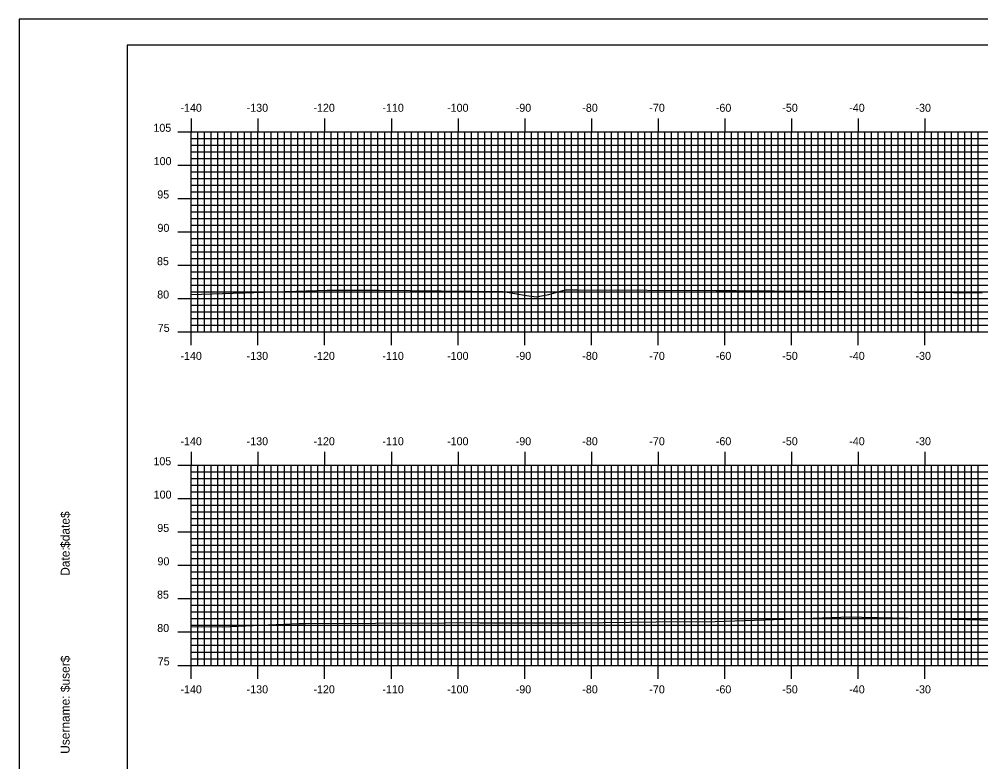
# Model space of a CAD drawing. Extents: x 2453 to 2796, y -1658 to -1438.
# Drawn here: x 2452.9 to 2597.1, y -1549.1 to -1437.7 of the extents above; entities that cross this region are included whole.
import ezdxf

# ---------------------------------------------------------------- set-up
doc = ezdxf.new("R2010")
doc.units = 0
for name, color, linetype in [('BORDER', 7, 'Continuous'), ('H_V ANNOTATION', 7, 'Continuous'), ('MAJOR', 7, 'Continuous'), ('MINOR', 7, 'Continuous'), ('PLOT BOUNDARY', 7, 'Continuous'), ('S_Roadway_Centerline', 7, 'Continuous')]:
    doc.layers.add(name, color=color, linetype=linetype)

msp = doc.modelspace()

# ---------------------------------------------------------------- linework, layer by layer
at = {"layer": 'BORDER'}
msp.add_lwpolyline([(2469.1, -1651.6), (2789.1, -1651.6), (2789.1, -1441.6), (2469.1, -1441.6)], close=True, dxfattribs=at)
at = {"layer": 'MAJOR'}
for p, q in [((2478.7, -1452.6), (2478.7, -1454.6)), ((2488.7, -1452.6), (2488.7, -1454.6)), ((2498.7, -1452.6), (2498.7, -1454.6)), ((2508.7, -1452.6), (2508.7, -1454.6)), ((2518.7, -1452.6), (2518.7, -1454.6)), ((2528.7, -1452.6), (2528.7, -1454.6)), ((2538.7, -1452.6), (2538.7, -1454.6)), ((2548.7, -1452.6), (2548.7, -1454.6)), ((2558.7, -1452.6), (2558.7, -1454.6)), ((2568.7, -1452.6), (2568.7, -1454.6)), ((2578.7, -1452.6), (2578.7, -1454.6)), ((2588.7, -1452.6), (2588.7, -1454.6)), ((2476.7, -1454.6), (2478.7, -1454.6)), ((2478.7, -1454.6), (2758.7, -1454.6)), ((2478.7, -1484.6), (2478.7, -1454.6)), ((2478.7, -1484.6), (2478.7, -1454.6)), ((2478.7, -1454.6), (2758.7, -1454.6)), ((2488.7, -1484.6), (2488.7, -1454.6)), ((2498.7, -1484.6), (2498.7, -1454.6)), ((2508.7, -1484.6), (2508.7, -1454.6)), ((2518.7, -1484.6), (2518.7, -1454.6)), ((2528.7, -1484.6), (2528.7, -1454.6)), ((2538.7, -1484.6), (2538.7, -1454.6)), ((2548.7, -1484.6), (2548.7, -1454.6)), ((2558.7, -1484.6), (2558.7, -1454.6)), ((2568.7, -1484.6), (2568.7, -1454.6)), ((2578.7, -1484.6), (2578.7, -1454.6)), ((2588.7, -1484.6), (2588.7, -1454.6)), ((2476.7, -1459.6), (2478.7, -1459.6)), ((2478.7, -1459.6), (2758.7, -1459.6)), ((2476.7, -1464.6), (2478.7, -1464.6)), ((2478.7, -1464.6), (2758.7, -1464.6)), ((2476.7, -1469.6), (2478.7, -1469.6)), ((2478.7, -1469.6), (2758.7, -1469.6)), ((2476.7, -1474.6), (2478.7, -1474.6)), ((2478.7, -1474.6), (2758.7, -1474.6)), ((2476.7, -1479.6), (2478.7, -1479.6)), ((2478.7, -1479.6), (2758.7, -1479.6)), ((2476.7, -1484.6), (2478.7, -1484.6)), ((2478.7, -1484.6), (2758.7, -1484.6)), ((2478.7, -1484.6), (2758.7, -1484.6)), ((2478.7, -1486.61), (2478.7, -1484.6)), ((2488.7, -1486.61), (2488.7, -1484.6)), ((2498.7, -1486.61), (2498.7, -1484.6)), ((2508.7, -1486.61), (2508.7, -1484.6)), ((2518.7, -1486.61), (2518.7, -1484.6)), ((2528.7, -1486.61), (2528.7, -1484.6)), ((2538.7, -1486.61), (2538.7, -1484.6)), ((2548.7, -1486.61), (2548.7, -1484.6)), ((2558.7, -1486.61), (2558.7, -1484.6)), ((2568.7, -1486.61), (2568.7, -1484.6)), ((2578.7, -1486.61), (2578.7, -1484.6)), ((2588.7, -1486.61), (2588.7, -1484.6)), ((2478.7, -1502.6), (2478.7, -1504.6)), ((2488.7, -1502.6), (2488.7, -1504.6)), ((2498.7, -1502.6), (2498.7, -1504.6)), ((2508.7, -1502.6), (2508.7, -1504.6)), ((2518.7, -1502.6), (2518.7, -1504.6)), ((2528.7, -1502.6), (2528.7, -1504.6)), ((2538.7, -1502.6), (2538.7, -1504.6)), ((2548.7, -1502.6), (2548.7, -1504.6)), ((2558.7, -1502.6), (2558.7, -1504.6)), ((2568.7, -1502.6), (2568.7, -1504.6)), ((2578.7, -1502.6), (2578.7, -1504.6)), ((2588.7, -1502.6), (2588.7, -1504.6)), ((2476.7, -1504.6), (2478.7, -1504.6)), ((2478.7, -1504.6), (2758.7, -1504.6)), ((2478.7, -1534.6), (2478.7, -1504.6)), ((2478.7, -1534.6), (2478.7, -1504.6)), ((2478.7, -1504.6), (2758.7, -1504.6)), ((2488.7, -1534.6), (2488.7, -1504.6)), ((2498.7, -1534.6), (2498.7, -1504.6)), ((2508.7, -1534.6), (2508.7, -1504.6)), ((2518.7, -1534.6), (2518.7, -1504.6)), ((2528.7, -1534.6), (2528.7, -1504.6)), ((2538.7, -1534.6), (2538.7, -1504.6)), ((2548.7, -1534.6), (2548.7, -1504.6)), ((2558.7, -1534.6), (2558.7, -1504.6)), ((2568.7, -1534.6), (2568.7, -1504.6)), ((2578.7, -1534.6), (2578.7, -1504.6)), ((2588.7, -1534.6), (2588.7, -1504.6)), ((2476.7, -1509.6), (2478.7, -1509.6)), ((2478.7, -1509.6), (2758.7, -1509.6)), ((2476.7, -1514.6), (2478.7, -1514.6)), ((2478.7, -1514.6), (2758.7, -1514.6)), ((2476.7, -1519.6), (2478.7, -1519.6)), ((2478.7, -1519.6), (2758.7, -1519.6)), ((2476.7, -1524.6), (2478.7, -1524.6)), ((2478.7, -1524.6), (2758.7, -1524.6)), ((2476.7, -1529.6), (2478.7, -1529.6)), ((2478.7, -1529.6), (2758.7, -1529.6)), ((2476.7, -1534.6), (2478.7, -1534.6)), ((2478.7, -1534.6), (2758.7, -1534.6)), ((2478.7, -1534.6), (2758.7, -1534.6)), ((2478.7, -1536.61), (2478.7, -1534.6)), ((2488.7, -1536.61), (2488.7, -1534.6)), ((2498.7, -1536.61), (2498.7, -1534.6)), ((2508.7, -1536.61), (2508.7, -1534.6)), ((2518.7, -1536.61), (2518.7, -1534.6)), ((2528.7, -1536.61), (2528.7, -1534.6)), ((2538.7, -1536.61), (2538.7, -1534.6)), ((2548.7, -1536.61), (2548.7, -1534.6)), ((2558.7, -1536.61), (2558.7, -1534.6)), ((2568.7, -1536.61), (2568.7, -1534.6)), ((2578.7, -1536.61), (2578.7, -1534.6)), ((2588.7, -1536.61), (2588.7, -1534.6))]:
    msp.add_line(p, q, dxfattribs=at)
at = {"layer": 'MINOR'}
for p, q in [((2478.7, -1455.6), (2758.7, -1455.6)), ((2478.7, -1455.6), (2480.7, -1455.6)), ((2479.7, -1484.6), (2479.7, -1454.6)), ((2480.7, -1484.6), (2480.7, -1454.6)), ((2481.7, -1484.6), (2481.7, -1454.6)), ((2482.7, -1484.6), (2482.7, -1454.6)), ((2483.7, -1484.6), (2483.7, -1454.6)), ((2484.7, -1484.6), (2484.7, -1454.6)), ((2485.7, -1484.6), (2485.7, -1454.6)), ((2486.7, -1484.6), (2486.7, -1454.6)), ((2487.7, -1484.6), (2487.7, -1454.6)), ((2489.7, -1484.6), (2489.7, -1454.6)), ((2490.7, -1484.6), (2490.7, -1454.6)), ((2491.7, -1484.6), (2491.7, -1454.6)), ((2492.7, -1484.6), (2492.7, -1454.6)), ((2493.7, -1484.6), (2493.7, -1454.6)), ((2494.7, -1484.6), (2494.7, -1454.6)), ((2495.7, -1484.6), (2495.7, -1454.6)), ((2496.7, -1484.6), (2496.7, -1454.6)), ((2497.7, -1484.6), (2497.7, -1454.6)), ((2499.7, -1484.6), (2499.7, -1454.6)), ((2500.7, -1484.6), (2500.7, -1454.6)), ((2501.7, -1484.6), (2501.7, -1454.6)), ((2502.7, -1484.6), (2502.7, -1454.6)), ((2503.7, -1484.6), (2503.7, -1454.6)), ((2504.7, -1484.6), (2504.7, -1454.6)), ((2505.7, -1484.6), (2505.7, -1454.6)), ((2506.7, -1484.6), (2506.7, -1454.6)), ((2507.7, -1484.6), (2507.7, -1454.6)), ((2509.7, -1484.6), (2509.7, -1454.6)), ((2510.7, -1484.6), (2510.7, -1454.6)), ((2511.7, -1484.6), (2511.7, -1454.6)), ((2512.7, -1484.6), (2512.7, -1454.6)), ((2513.7, -1484.6), (2513.7, -1454.6)), ((2514.7, -1484.6), (2514.7, -1454.6)), ((2515.7, -1484.6), (2515.7, -1454.6)), ((2516.7, -1484.6), (2516.7, -1454.6)), ((2517.7, -1484.6), (2517.7, -1454.6)), ((2519.7, -1484.6), (2519.7, -1454.6)), ((2520.7, -1484.6), (2520.7, -1454.6)), ((2521.7, -1484.6), (2521.7, -1454.6)), ((2522.7, -1484.6), (2522.7, -1454.6)), ((2523.7, -1484.6), (2523.7, -1454.6)), ((2524.7, -1484.6), (2524.7, -1454.6)), ((2525.7, -1484.6), (2525.7, -1454.6)), ((2526.7, -1484.6), (2526.7, -1454.6)), ((2527.7, -1484.6), (2527.7, -1454.6)), ((2529.7, -1484.6), (2529.7, -1454.6)), ((2530.7, -1484.6), (2530.7, -1454.6)), ((2531.7, -1484.6), (2531.7, -1454.6)), ((2532.7, -1484.6), (2532.7, -1454.6)), ((2533.7, -1484.6), (2533.7, -1454.6)), ((2534.7, -1484.6), (2534.7, -1454.6)), ((2535.7, -1484.6), (2535.7, -1454.6)), ((2536.7, -1484.6), (2536.7, -1454.6)), ((2537.7, -1484.6), (2537.7, -1454.6)), ((2539.7, -1484.6), (2539.7, -1454.6)), ((2540.7, -1484.6), (2540.7, -1454.6)), ((2541.7, -1484.6), (2541.7, -1454.6)), ((2542.7, -1484.6), (2542.7, -1454.6)), ((2543.7, -1484.6), (2543.7, -1454.6)), ((2544.7, -1484.6), (2544.7, -1454.6)), ((2545.7, -1484.6), (2545.7, -1454.6)), ((2546.7, -1484.6), (2546.7, -1454.6)), ((2547.7, -1484.6), (2547.7, -1454.6)), ((2549.7, -1484.6), (2549.7, -1454.6)), ((2550.7, -1484.6), (2550.7, -1454.6)), ((2551.7, -1484.6), (2551.7, -1454.6)), ((2552.7, -1484.6), (2552.7, -1454.6)), ((2553.7, -1484.6), (2553.7, -1454.6)), ((2554.7, -1484.6), (2554.7, -1454.6)), ((2555.7, -1484.6), (2555.7, -1454.6)), ((2556.7, -1484.6), (2556.7, -1454.6)), ((2557.7, -1484.6), (2557.7, -1454.6)), ((2559.7, -1484.6), (2559.7, -1454.6)), ((2560.7, -1484.6), (2560.7, -1454.6)), ((2561.7, -1484.6), (2561.7, -1454.6)), ((2562.7, -1484.6), (2562.7, -1454.6)), ((2563.7, -1484.6), (2563.7, -1454.6)), ((2564.7, -1484.6), (2564.7, -1454.6)), ((2565.7, -1484.6), (2565.7, -1454.6)), ((2566.7, -1484.6), (2566.7, -1454.6)), ((2567.7, -1484.6), (2567.7, -1454.6)), ((2569.7, -1484.6), (2569.7, -1454.6)), ((2570.7, -1484.6), (2570.7, -1454.6)), ((2571.7, -1484.6), (2571.7, -1454.6)), ((2572.7, -1484.6), (2572.7, -1454.6)), ((2573.7, -1484.6), (2573.7, -1454.6)), ((2574.7, -1484.6), (2574.7, -1454.6)), ((2575.7, -1484.6), (2575.7, -1454.6)), ((2576.7, -1484.6), (2576.7, -1454.6)), ((2577.7, -1484.6), (2577.7, -1454.6)), ((2579.7, -1484.6), (2579.7, -1454.6)), ((2580.7, -1484.6), (2580.7, -1454.6)), ((2581.7, -1484.6), (2581.7, -1454.6)), ((2582.7, -1484.6), (2582.7, -1454.6)), ((2583.7, -1484.6), (2583.7, -1454.6)), ((2584.7, -1484.6), (2584.7, -1454.6)), ((2585.7, -1484.6), (2585.7, -1454.6)), ((2586.7, -1484.6), (2586.7, -1454.6)), ((2587.7, -1484.6), (2587.7, -1454.6)), ((2589.7, -1484.6), (2589.7, -1454.6)), ((2590.7, -1484.6), (2590.7, -1454.6)), ((2591.7, -1484.6), (2591.7, -1454.6)), ((2592.7, -1484.6), (2592.7, -1454.6)), ((2593.7, -1484.6), (2593.7, -1454.6)), ((2594.7, -1484.6), (2594.7, -1454.6)), ((2595.7, -1484.6), (2595.7, -1454.6)), ((2596.7, -1484.6), (2596.7, -1454.6)), ((2478.7, -1456.6), (2758.7, -1456.6)), ((2478.7, -1456.6), (2480.7, -1456.6)), ((2478.7, -1457.6), (2758.7, -1457.6)), ((2478.7, -1457.6), (2480.7, -1457.6)), ((2478.7, -1458.6), (2758.7, -1458.6)), ((2478.7, -1458.6), (2480.7, -1458.6)), ((2478.7, -1460.6), (2758.7, -1460.6)), ((2478.7, -1460.6), (2480.7, -1460.6)), ((2478.7, -1461.6), (2758.7, -1461.6)), ((2478.7, -1461.6), (2480.7, -1461.6)), ((2478.7, -1462.6), (2758.7, -1462.6)), ((2478.7, -1462.6), (2480.7, -1462.6)), ((2478.7, -1463.6), (2758.7, -1463.6)), ((2478.7, -1463.6), (2480.7, -1463.6)), ((2478.7, -1465.6), (2758.7, -1465.6)), ((2478.7, -1465.6), (2480.7, -1465.6)), ((2478.7, -1466.6), (2758.7, -1466.6)), ((2478.7, -1466.6), (2480.7, -1466.6)), ((2478.7, -1467.6), (2758.7, -1467.6)), ((2478.7, -1467.6), (2480.7, -1467.6)), ((2478.7, -1468.6), (2758.7, -1468.6)), ((2478.7, -1468.6), (2480.7, -1468.6)), ((2478.7, -1470.6), (2758.7, -1470.6)), ((2478.7, -1470.6), (2480.7, -1470.6)), ((2478.7, -1471.6), (2758.7, -1471.6)), ((2478.7, -1471.6), (2480.7, -1471.6)), ((2478.7, -1472.6), (2758.7, -1472.6)), ((2478.7, -1472.6), (2480.7, -1472.6)), ((2478.7, -1473.6), (2758.7, -1473.6)), ((2478.7, -1473.6), (2480.7, -1473.6)), ((2478.7, -1475.6), (2758.7, -1475.6)), ((2478.7, -1475.6), (2480.7, -1475.6)), ((2478.7, -1476.6), (2758.7, -1476.6)), ((2478.7, -1476.6), (2480.7, -1476.6)), ((2478.7, -1477.6), (2758.7, -1477.6)), ((2478.7, -1477.6), (2480.7, -1477.6)), ((2478.7, -1478.6), (2758.7, -1478.6)), ((2478.7, -1478.6), (2480.7, -1478.6)), ((2478.7, -1480.6), (2758.7, -1480.6)), ((2478.7, -1480.6), (2480.7, -1480.6)), ((2478.7, -1481.6), (2758.7, -1481.6)), ((2478.7, -1481.6), (2480.7, -1481.6)), ((2478.7, -1482.6), (2758.7, -1482.6)), ((2478.7, -1482.6), (2480.7, -1482.6)), ((2478.7, -1483.6), (2758.7, -1483.6)), ((2478.7, -1483.6), (2480.7, -1483.6)), ((2479.7, -1534.6), (2479.7, -1504.6)), ((2480.7, -1534.6), (2480.7, -1504.6)), ((2481.7, -1534.6), (2481.7, -1504.6)), ((2482.7, -1534.6), (2482.7, -1504.6)), ((2483.7, -1534.6), (2483.7, -1504.6)), ((2484.7, -1534.6), (2484.7, -1504.6)), ((2485.7, -1534.6), (2485.7, -1504.6)), ((2486.7, -1534.6), (2486.7, -1504.6)), ((2487.7, -1534.6), (2487.7, -1504.6)), ((2489.7, -1534.6), (2489.7, -1504.6)), ((2490.7, -1534.6), (2490.7, -1504.6)), ((2491.7, -1534.6), (2491.7, -1504.6)), ((2492.7, -1534.6), (2492.7, -1504.6)), ((2493.7, -1534.6), (2493.7, -1504.6)), ((2494.7, -1534.6), (2494.7, -1504.6)), ((2495.7, -1534.6), (2495.7, -1504.6)), ((2496.7, -1534.6), (2496.7, -1504.6)), ((2497.7, -1534.6), (2497.7, -1504.6)), ((2499.7, -1534.6), (2499.7, -1504.6)), ((2500.7, -1534.6), (2500.7, -1504.6)), ((2501.7, -1534.6), (2501.7, -1504.6)), ((2502.7, -1534.6), (2502.7, -1504.6)), ((2503.7, -1534.6), (2503.7, -1504.6)), ((2504.7, -1534.6), (2504.7, -1504.6)), ((2505.7, -1534.6), (2505.7, -1504.6)), ((2506.7, -1534.6), (2506.7, -1504.6)), ((2507.7, -1534.6), (2507.7, -1504.6)), ((2509.7, -1534.6), (2509.7, -1504.6)), ((2510.7, -1534.6), (2510.7, -1504.6)), ((2511.7, -1534.6), (2511.7, -1504.6)), ((2512.7, -1534.6), (2512.7, -1504.6)), ((2513.7, -1534.6), (2513.7, -1504.6)), ((2514.7, -1534.6), (2514.7, -1504.6)), ((2515.7, -1534.6), (2515.7, -1504.6)), ((2516.7, -1534.6), (2516.7, -1504.6)), ((2517.7, -1534.6), (2517.7, -1504.6)), ((2519.7, -1534.6), (2519.7, -1504.6)), ((2520.7, -1534.6), (2520.7, -1504.6)), ((2521.7, -1534.6), (2521.7, -1504.6)), ((2522.7, -1534.6), (2522.7, -1504.6)), ((2523.7, -1534.6), (2523.7, -1504.6)), ((2524.7, -1534.6), (2524.7, -1504.6)), ((2525.7, -1534.6), (2525.7, -1504.6)), ((2526.7, -1534.6), (2526.7, -1504.6)), ((2527.7, -1534.6), (2527.7, -1504.6)), ((2529.7, -1534.6), (2529.7, -1504.6)), ((2530.7, -1534.6), (2530.7, -1504.6)), ((2531.7, -1534.6), (2531.7, -1504.6)), ((2532.7, -1534.6), (2532.7, -1504.6)), ((2533.7, -1534.6), (2533.7, -1504.6)), ((2534.7, -1534.6), (2534.7, -1504.6)), ((2535.7, -1534.6), (2535.7, -1504.6)), ((2536.7, -1534.6), (2536.7, -1504.6)), ((2537.7, -1534.6), (2537.7, -1504.6)), ((2539.7, -1534.6), (2539.7, -1504.6)), ((2540.7, -1534.6), (2540.7, -1504.6)), ((2541.7, -1534.6), (2541.7, -1504.6)), ((2542.7, -1534.6), (2542.7, -1504.6)), ((2543.7, -1534.6), (2543.7, -1504.6)), ((2544.7, -1534.6), (2544.7, -1504.6)), ((2545.7, -1534.6), (2545.7, -1504.6)), ((2546.7, -1534.6), (2546.7, -1504.6)), ((2547.7, -1534.6), (2547.7, -1504.6)), ((2549.7, -1534.6), (2549.7, -1504.6)), ((2550.7, -1534.6), (2550.7, -1504.6)), ((2551.7, -1534.6), (2551.7, -1504.6)), ((2552.7, -1534.6), (2552.7, -1504.6)), ((2553.7, -1534.6), (2553.7, -1504.6)), ((2554.7, -1534.6), (2554.7, -1504.6)), ((2555.7, -1534.6), (2555.7, -1504.6)), ((2556.7, -1534.6), (2556.7, -1504.6)), ((2557.7, -1534.6), (2557.7, -1504.6)), ((2559.7, -1534.6), (2559.7, -1504.6)), ((2560.7, -1534.6), (2560.7, -1504.6)), ((2561.7, -1534.6), (2561.7, -1504.6)), ((2562.7, -1534.6), (2562.7, -1504.6)), ((2563.7, -1534.6), (2563.7, -1504.6)), ((2564.7, -1534.6), (2564.7, -1504.6)), ((2565.7, -1534.6), (2565.7, -1504.6)), ((2566.7, -1534.6), (2566.7, -1504.6)), ((2567.7, -1534.6), (2567.7, -1504.6)), ((2569.7, -1534.6), (2569.7, -1504.6)), ((2570.7, -1534.6), (2570.7, -1504.6)), ((2571.7, -1534.6), (2571.7, -1504.6)), ((2572.7, -1534.6), (2572.7, -1504.6)), ((2573.7, -1534.6), (2573.7, -1504.6)), ((2574.7, -1534.6), (2574.7, -1504.6)), ((2575.7, -1534.6), (2575.7, -1504.6)), ((2576.7, -1534.6), (2576.7, -1504.6)), ((2577.7, -1534.6), (2577.7, -1504.6)), ((2579.7, -1534.6), (2579.7, -1504.6)), ((2580.7, -1534.6), (2580.7, -1504.6)), ((2581.7, -1534.6), (2581.7, -1504.6)), ((2582.7, -1534.6), (2582.7, -1504.6)), ((2583.7, -1534.6), (2583.7, -1504.6)), ((2584.7, -1534.6), (2584.7, -1504.6)), ((2585.7, -1534.6), (2585.7, -1504.6)), ((2586.7, -1534.6), (2586.7, -1504.6)), ((2587.7, -1534.6), (2587.7, -1504.6)), ((2589.7, -1534.6), (2589.7, -1504.6)), ((2590.7, -1534.6), (2590.7, -1504.6)), ((2591.7, -1534.6), (2591.7, -1504.6)), ((2592.7, -1534.6), (2592.7, -1504.6)), ((2593.7, -1534.6), (2593.7, -1504.6)), ((2594.7, -1534.6), (2594.7, -1504.6)), ((2595.7, -1534.6), (2595.7, -1504.6)), ((2596.7, -1534.6), (2596.7, -1504.6)), ((2478.7, -1505.6), (2758.7, -1505.6)), ((2478.7, -1505.6), (2480.7, -1505.6)), ((2478.7, -1506.6), (2758.7, -1506.6)), ((2478.7, -1506.6), (2480.7, -1506.6)), ((2478.7, -1507.6), (2758.7, -1507.6)), ((2478.7, -1507.6), (2480.7, -1507.6)), ((2478.7, -1508.6), (2758.7, -1508.6)), ((2478.7, -1508.6), (2480.7, -1508.6)), ((2478.7, -1510.6), (2758.7, -1510.6)), ((2478.7, -1510.6), (2480.7, -1510.6)), ((2478.7, -1511.6), (2758.7, -1511.6)), ((2478.7, -1511.6), (2480.7, -1511.6)), ((2478.7, -1512.6), (2758.7, -1512.6)), ((2478.7, -1512.6), (2480.7, -1512.6)), ((2478.7, -1513.6), (2758.7, -1513.6)), ((2478.7, -1513.6), (2480.7, -1513.6)), ((2478.7, -1515.6), (2758.7, -1515.6)), ((2478.7, -1515.6), (2480.7, -1515.6)), ((2478.7, -1516.6), (2758.7, -1516.6)), ((2478.7, -1516.6), (2480.7, -1516.6)), ((2478.7, -1517.6), (2758.7, -1517.6)), ((2478.7, -1517.6), (2480.7, -1517.6)), ((2478.7, -1518.6), (2758.7, -1518.6)), ((2478.7, -1518.6), (2480.7, -1518.6)), ((2478.7, -1520.6), (2758.7, -1520.6)), ((2478.7, -1520.6), (2480.7, -1520.6)), ((2478.7, -1521.6), (2758.7, -1521.6)), ((2478.7, -1521.6), (2480.7, -1521.6)), ((2478.7, -1522.6), (2758.7, -1522.6)), ((2478.7, -1522.6), (2480.7, -1522.6)), ((2478.7, -1523.6), (2758.7, -1523.6)), ((2478.7, -1523.6), (2480.7, -1523.6)), ((2478.7, -1525.6), (2758.7, -1525.6)), ((2478.7, -1525.6), (2480.7, -1525.6)), ((2478.7, -1526.6), (2758.7, -1526.6)), ((2478.7, -1526.6), (2480.7, -1526.6)), ((2478.7, -1527.6), (2758.7, -1527.6)), ((2478.7, -1527.6), (2480.7, -1527.6)), ((2478.7, -1528.6), (2758.7, -1528.6)), ((2478.7, -1528.6), (2480.7, -1528.6)), ((2478.7, -1530.6), (2758.7, -1530.6)), ((2478.7, -1530.6), (2480.7, -1530.6)), ((2478.7, -1531.6), (2758.7, -1531.6)), ((2478.7, -1531.6), (2480.7, -1531.6)), ((2478.7, -1532.6), (2758.7, -1532.6)), ((2478.7, -1532.6), (2480.7, -1532.6)), ((2478.7, -1533.6), (2758.7, -1533.6)), ((2478.7, -1533.6), (2480.7, -1533.6))]:
    msp.add_line(p, q, dxfattribs=at)
at = {"layer": 'PLOT BOUNDARY'}
msp.add_lwpolyline([(2452.91, -1657.72), (2792.91, -1657.72), (2792.91, -1437.72), (2452.91, -1437.72)], close=True, dxfattribs=at)
at = {"layer": 'S_Roadway_Centerline'}
for points in [[(2478.7, -1478.98), (2499.06, -1478.33), (2506.87, -1478.33), (2525.46, -1478.55), (2528.98, -1479.16), (2530.39, -1479.35), (2532.29, -1479), (2534.77, -1478.3), (2536.75, -1478.29), (2557.41, -1478.4), (2558.39, -1478.42), (2560.39, -1478.41), (2571.81, -1478.48), (2587.14, -1478.63), (2588.65, -1478.67), (2597.27, -1478.77)], [(2478.7, -1528.77), (2483.39, -1528.81), (2494.87, -1528.32), (2495.04, -1528.32), (2495.83, -1528.31), (2516.82, -1528.21), (2519.01, -1528.18), (2521.96, -1528.24), (2536.46, -1528.24), (2548.42, -1528.08), (2557.26, -1528.01), (2574.77, -1527.44), (2577.39, -1527.34), (2579.26, -1527.4), (2590.78, -1527.62), (2599.13, -1527.85)]]:
    msp.add_lwpolyline(points, dxfattribs=at)

# ---------------------------------------------------------------- texts
at = {"layer": 'BORDER'}
for s, p in [('$date$', (2460.47, -1516.99)), ('Date:', (2460.47, -1521.17)), ('$user$', (2460.47, -1538.62)), ('Username:', (2460.47, -1547.87))]:
    msp.add_text(s, height=1.339, rotation=90, dxfattribs=at).set_placement(p)
at = {"layer": 'H_V ANNOTATION'}
for s, p in [('-140', (2477.08, -1451.6)), ('-130', (2487.01, -1451.6)), ('-120', (2497.02, -1451.6)), ('-110', (2507.36, -1451.6)), ('-100', (2517.06, -1451.6)), ('-90', (2527.35, -1451.6)), ('-80', (2537.33, -1451.6)), ('-70', (2547.38, -1451.6)), ('-60', (2557.35, -1451.6)), ('-50', (2567.31, -1451.6)), ('-40', (2577.35, -1451.6)), ('-30', (2587.28, -1451.6)), ('105', (2473.03, -1454.6)), ('100', (2473.07, -1459.6)), ('95', (2473.61, -1464.6)), ('90', (2473.64, -1469.6)), ('85', (2473.57, -1474.6)), ('80', (2473.6, -1479.6)), ('75', (2473.68, -1484.6)), ('-140', (2477.08, -1488.8)), ('-130', (2487.01, -1488.8)), ('-120', (2497.02, -1488.8)), ('-110', (2507.36, -1488.8)), ('-100', (2517.06, -1488.8)), ('-90', (2527.35, -1488.8)), ('-80', (2537.33, -1488.8)), ('-70', (2547.38, -1488.8)), ('-60', (2557.35, -1488.8)), ('-50', (2567.31, -1488.8)), ('-40', (2577.35, -1488.8)), ('-30', (2587.28, -1488.8)), ('-140', (2477.08, -1501.6)), ('-130', (2487.01, -1501.6)), ('-120', (2497.02, -1501.6)), ('-110', (2507.36, -1501.6)), ('-100', (2517.06, -1501.6)), ('-90', (2527.35, -1501.6)), ('-80', (2537.33, -1501.6)), ('-70', (2547.38, -1501.6)), ('-60', (2557.35, -1501.6)), ('-50', (2567.31, -1501.6)), ('-40', (2577.35, -1501.6)), ('-30', (2587.28, -1501.6)), ('105', (2473.03, -1504.6)), ('100', (2473.07, -1509.6)), ('95', (2473.61, -1514.6)), ('90', (2473.64, -1519.6)), ('85', (2473.57, -1524.6)), ('80', (2473.6, -1529.6)), ('75', (2473.68, -1534.6)), ('-140', (2477.08, -1538.8)), ('-130', (2487.01, -1538.8)), ('-120', (2497.02, -1538.8)), ('-110', (2507.36, -1538.8)), ('-100', (2517.06, -1538.8)), ('-90', (2527.35, -1538.8)), ('-80', (2537.33, -1538.8)), ('-70', (2547.38, -1538.8)), ('-60', (2557.35, -1538.8)), ('-50', (2567.31, -1538.8)), ('-40', (2577.35, -1538.8)), ('-30', (2587.28, -1538.8))]:
    msp.add_text(s, height=1.2, dxfattribs=at).set_placement(p)
at = {"layer": 'MAJOR'}
for p in [(2478.69, -1484.6), (2478.69, -1534.6)]:
    msp.add_text('-', height=0.012, dxfattribs=at).set_placement(p)

doc.saveas('drawing.dxf')
